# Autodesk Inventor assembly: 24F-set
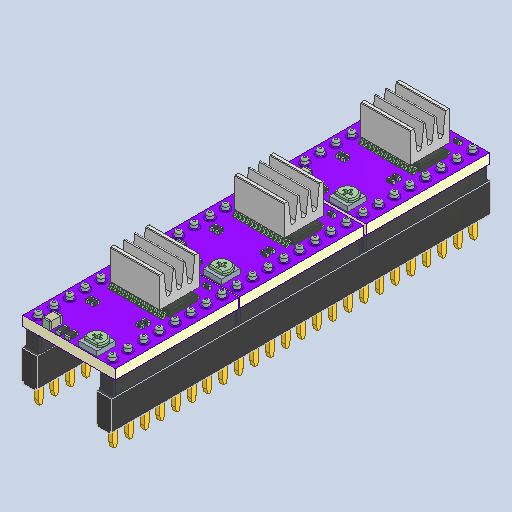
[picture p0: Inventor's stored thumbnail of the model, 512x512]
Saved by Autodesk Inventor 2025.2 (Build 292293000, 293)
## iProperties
Created: 2025-04
Part Number: 24F-set
Description: PART--DESC
Document SubType Name: Assembly
Designer: BennF
Author: BennF
Revision Number: NONE
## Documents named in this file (6)
- C:\Users\BennF\Nextcloud\Benutzer\CNC JarBeRi\existing parts\Electronics\RepRap A4988 Shied (USE WITHOUT ARDUINO)\reprap-a4988-1.snapshot.1\RepRap\RepRap\24F-set.iam
- C:\Users\BennF\Nextcloud\Benutzer\CNC JarBeRi\existing parts\Electronics\RepRap A4988 Shied (USE WITHOUT ARDUINO)\reprap-a4988-1.snapshot.1\RepRap\RepRap\DRV 8825_2.iam
- C:\Users\BennF\Nextcloud\Benutzer\CNC JarBeRi\existing parts\Electronics\RepRap A4988 Shied (USE WITHOUT ARDUINO)\reprap-a4988-1.snapshot.1\RepRap\RepRap\DRV 8825_3.iam
- C:\Users\BennF\Nextcloud\Benutzer\CNC JarBeRi\existing parts\Electronics\RepRap A4988 Shied (USE WITHOUT ARDUINO)\reprap-a4988-1.snapshot.1\RepRap\RepRap\DRV 8825_4.iam
- C:\Users\BennF\Nextcloud\Benutzer\CNC JarBeRi\existing parts\Electronics\RepRap A4988 Shied (USE WITHOUT ARDUINO)\reprap-a4988-1.snapshot.1\RepRap\RepRap\24F.iam
- C:\Users\BennF\Nextcloud\Benutzer\CNC JarBeRi\existing parts\Electronics\RepRap A4988 Shied (USE WITHOUT ARDUINO)\reprap-a4988-1.snapshot.1\RepRap\RepRap\24F_1.iam
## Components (5 placed, 2 different names)
1. DRV 8825 [sub-assembly]
2. DRV 8825:1 [sub-assembly]
3. DRV 8825:2 [sub-assembly]
4. 24F [sub-assembly]
5. 24F:1 [sub-assembly]
